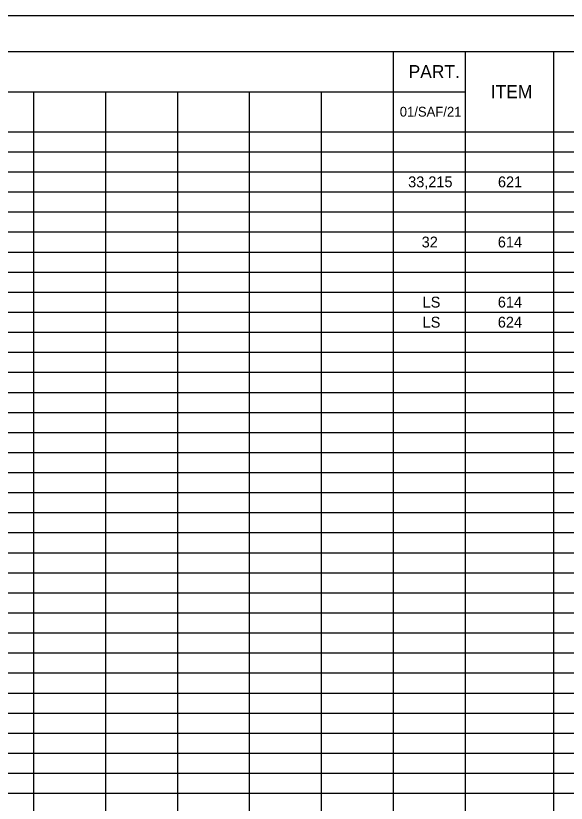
# Model space of a CAD drawing. Extents: x 0 to 34, y 0 to 22.
# Drawn here: x 9.29 to 16.97, y 11 to 22 of the extents above; entities that cross this region are included whole.
import ezdxf

# ---------------------------------------------------------------- set-up
doc = ezdxf.new("R2010")
doc.units = 0
for name, color, linetype in [('Default', 7, 'Continuous'), ('SH_Border', 7, 'Continuous'), ('SH_Cut_Line', 7, 'Continuous')]:
    doc.layers.add(name, color=color, linetype=linetype)

msp = doc.modelspace()

# ---------------------------------------------------------------- linework, layer by layer
at = {"layer": 'Default'}
for p, q in [((1.5, 21.5), (31.99, 21.5)), ((14.555, 21.5), (14.555, 0.51)), ((15.559, 21.5), (15.559, 0.51)), ((16.794, 21.5), (16.794, 0.51)), ((1.5, 20.94), (15.559, 20.94)), ((9.534, 20.94), (9.534, 0.51)), ((10.538, 20.94), (10.538, 0.51)), ((11.542, 20.94), (11.542, 0.51)), ((12.547, 20.94), (12.547, 0.51)), ((13.551, 20.94), (13.551, 0.51)), ((1.5, 20.381), (31.99, 20.381)), ((1.5, 20.101), (31.99, 20.101)), ((1.5, 19.821), (31.99, 19.821)), ((1.5, 19.541), (31.99, 19.541)), ((1.5, 19.261), (31.99, 19.261)), ((1.5, 18.981), (31.99, 18.981)), ((1.5, 18.701), (31.99, 18.701)), ((1.5, 18.421), (31.99, 18.421)), ((1.5, 18.142), (31.99, 18.142)), ((1.5, 17.862), (31.99, 17.862)), ((1.5, 17.582), (31.99, 17.582)), ((1.5, 17.302), (31.99, 17.302)), ((1.5, 17.022), (31.99, 17.022)), ((1.5, 16.742), (31.99, 16.742)), ((1.5, 16.462), (31.99, 16.462)), ((1.5, 16.182), (31.99, 16.182)), ((1.5, 15.903), (31.99, 15.903)), ((1.5, 15.623), (31.99, 15.623)), ((1.5, 15.343), (31.99, 15.343)), ((1.5, 15.063), (31.99, 15.063)), ((1.5, 14.783), (31.99, 14.783)), ((1.5, 14.503), (31.99, 14.503)), ((1.5, 14.223), (31.99, 14.223)), ((1.5, 13.943), (31.99, 13.943)), ((1.5, 13.664), (31.99, 13.664)), ((1.5, 13.384), (31.99, 13.384)), ((1.5, 13.104), (31.99, 13.104)), ((1.5, 12.824), (31.99, 12.824)), ((1.5, 12.544), (31.99, 12.544)), ((1.5, 12.264), (31.99, 12.264)), ((1.5, 11.984), (31.99, 11.984)), ((1.5, 11.705), (31.99, 11.705)), ((1.5, 11.425), (31.99, 11.425)), ((1.5, 11.145), (31.99, 11.145))]:
    msp.add_line(p, q, dxfattribs=at)
at = {"layer": 'SH_Border'}
msp.add_lwpolyline([(1.5, 21.5), (33.5, 21.5), (33.5, 0.5), (1.5, 0.5)], close=True, dxfattribs=at)
at = {"layer": 'SH_Cut_Line'}
msp.add_lwpolyline([(0, 0), (34, 0), (34, 22), (0, 22)], close=True, dxfattribs=at)

# ---------------------------------------------------------------- texts
at = {"layer": 'Default'}
for s, height, p in [('PART.', 0.1818, (14.771, 21.129)), ('ITEM', 0.1818, (15.919, 20.849)), ('01/SAF/21', 0.1363, (14.648, 20.592)), ('33,215', 0.1515, (14.765, 19.605)), ('621', 0.1515, (16.019, 19.605)), ('32', 0.1515, (14.954, 18.765)), ('614', 0.1515, (16.017, 18.765)), ('LS', 0.1515, (14.967, 17.926)), ('614', 0.1515, (16.017, 17.926)), ('LS', 0.1515, (14.967, 17.646)), ('624', 0.1515, (16.017, 17.646))]:
    msp.add_text(s, height=height, dxfattribs=at).set_placement(p)

doc.saveas('drawing.dxf')
